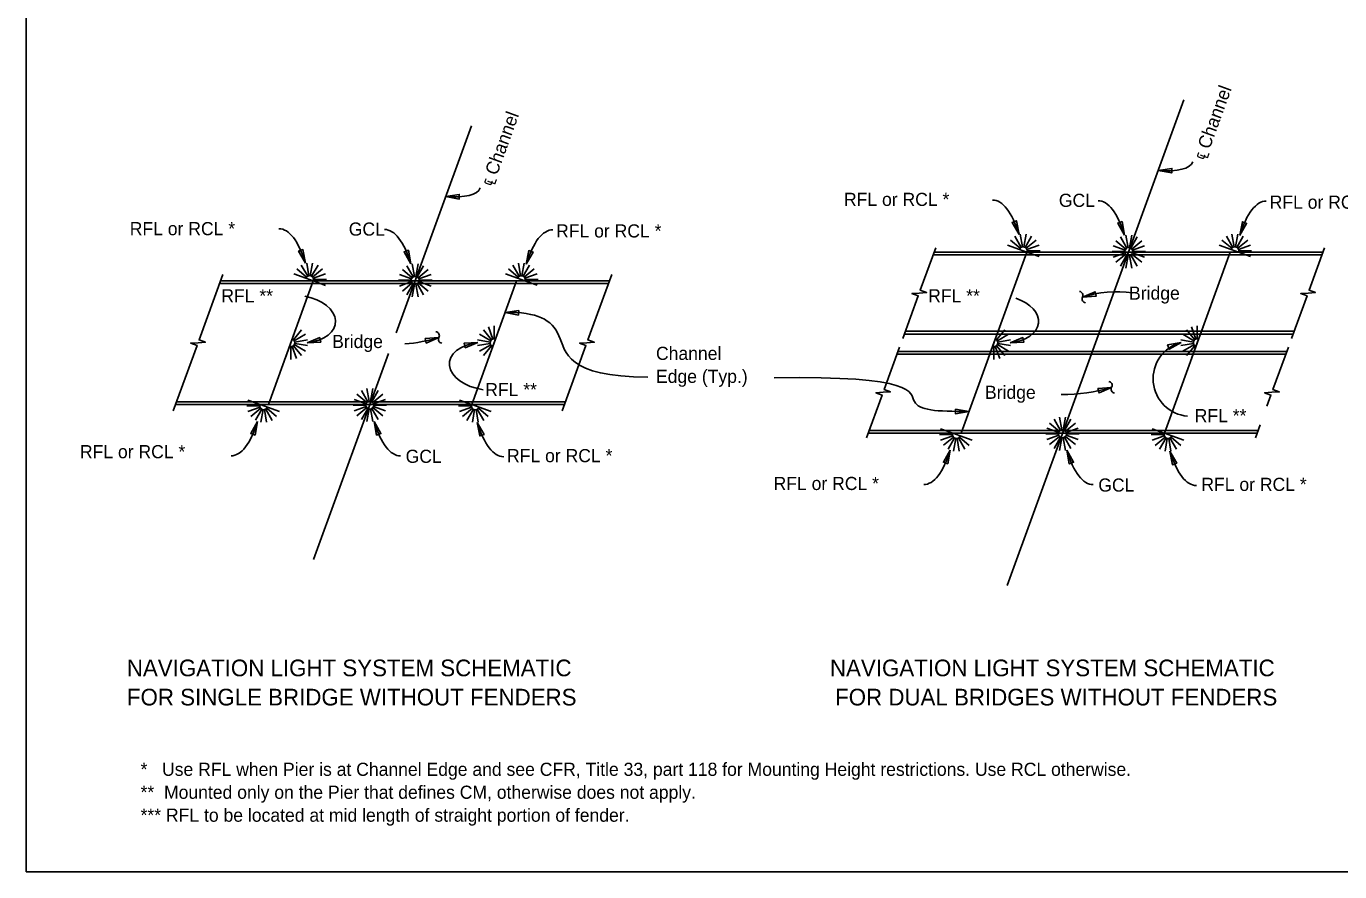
# Model space of a CAD drawing. Extents: x 0 to 1539, y 0 to 973.
# Drawn here: x 0 to 756, y 0 to 486 of the extents above; entities that cross this region are included whole.
import ezdxf

# ---------------------------------------------------------------- set-up
doc = ezdxf.new("R2010")
doc.units = 0
for name, color, linetype in [('Dimension', 7, 'Continuous'), ('Miscellaneous', 7, 'Continuous'), ('Miscellaneous1', 7, 'Continuous'), ('NavLight', 7, 'Continuous'), ('SupstrConc', 7, 'Continuous'), ('TextStructures', 7, 'Continuous')]:
    doc.layers.add(name, color=color, linetype=linetype)

msp = doc.modelspace()

# ---------------------------------------------------------------- linework, layer by layer
at = {"layer": 'Dimension'}
for points in [[(0, 0), (1539.4, 0), (1539.4, 972.98), (0, 972.98)], [(651.82, 403.57), (659.6, 402.1), (659.65, 404.75)], [(241.49, 388.54), (249.27, 387.07), (249.32, 389.71)], [(571.62, 366.77), (570.14, 374.55), (567.66, 373.63)], [(632.39, 366.36), (630.92, 374.15), (628.44, 373.23)], [(698.77, 366.2), (702.69, 373.08), (700.21, 373.99)], [(160.74, 350.23), (159.26, 358.01), (156.78, 357.09)], [(221.52, 349.82), (220.04, 357.6), (217.56, 356.68)], [(287.89, 349.66), (291.81, 356.53), (289.33, 357.44)], [(608.16, 330.66), (616.06, 331.21), (615.44, 333.78)], [(283.51, 320.29), (275.75, 321.86), (283.6, 322.94)], [(161.69, 304.25), (169.59, 304.8), (168.97, 307.37)], [(237.58, 307.39), (229.69, 306.75), (230.34, 304.18)], [(260.04, 304.6), (252.14, 304.05), (252.76, 301.48)], [(566.55, 304.25), (574.45, 304.8), (573.83, 307.37)], [(664.91, 304.59), (657.12, 303.16), (658.03, 300.67)], [(624.96, 278.73), (617.07, 278.09), (617.72, 275.52)], [(534.98, 266.17), (542.79, 264.82), (534.97, 263.52)], [(133.18, 259.05), (129.26, 252.18), (131.74, 251.27)], [(200.23, 259.02), (201.7, 251.24), (204.18, 252.16)], [(259.65, 258.53), (263.57, 251.65), (261.09, 250.74)], [(532.02, 242.51), (528.09, 235.63), (530.58, 234.72)], [(599.06, 242.48), (600.54, 234.69), (603.02, 235.61)], [(658.49, 241.98), (662.41, 235.11), (659.93, 234.2)]]:
    msp.add_lwpolyline(points, close=True, dxfattribs=at)
for points in [[(504.66, 306.82), (513.6, 331.38), (509.96, 332.7), (514.18, 332.96), (518.39, 333.22), (514.75, 334.55), (523.66, 359.02)], [(728.54, 306.82), (737.48, 331.38), (733.84, 332.7), (738.06, 332.96), (742.28, 333.22), (738.64, 334.55), (747.54, 359.02)], [(84.65, 265.19), (98.35, 302.83), (94.71, 304.16), (98.93, 304.42), (103.15, 304.68), (99.51, 306.01), (113.22, 343.69)], [(308.53, 265.19), (322.23, 302.83), (318.59, 304.16), (322.81, 304.42), (327.03, 304.68), (323.39, 306.01), (337.11, 343.69)], [(483.88, 249.73), (492.82, 274.29), (489.18, 275.62), (493.4, 275.88), (497.62, 276.14), (493.98, 277.46), (502.88, 301.93)], [(714.37, 267.87), (716.71, 274.29), (713.06, 275.62), (717.28, 275.88), (721.5, 276.14), (717.86, 277.46), (726.77, 301.93)], [(707.77, 249.73), (710.5, 257.24)]]:
    msp.add_lwpolyline(points, dxfattribs=at)
for centre, radius, start, end in [((606.2, 331.7), 2.24, 331.78441, 83.51163), ((627.83, 268.65), 65.06, 81.92792, 107.60511), ((610.14, 329.58), 2.24, 151.78441, 263.51163), ((235.62, 308.51), 2.24, 330.78819, 82.51541), ((209.68, 400.92), 97.6, 274.88318, 286.60889), ((239.52, 306.33), 2.24, 150.78819, 262.51541), ((670.44, 283.7), 21.61, 104.83071, 265.42671), ((623, 279.85), 2.24, 330.78819, 82.51541), ((597.07, 372.26), 97.6, 269.35418, 286.60889), ((626.91, 277.67), 2.24, 150.78819, 262.51541)]:
    msp.add_arc(centre, radius, start, end, dxfattribs=at)
for centre, major_axis, ratio, start_param, end_param in [((606.74, 434.59), (-65, 26.05), 0.265294, 2.43766, 3.141592), ((196.41, 419.56), (-65, 26.05), 0.265294, 2.43766, 3.141592), ((557.29, 329.23), (0.91, -57.27), 0.343516, 2.28027, 3.141592), ((618.06, 328.82), (0.91, -57.27), 0.343516, 2.28027, 3.141592), ((713.1, 328.65), (-0.91, -57.27), 0.343516, 3.141594, 4.002916), ((146.41, 312.69), (0.91, -57.27), 0.343516, 2.28027, 3.141592), ((207.18, 312.28), (0.91, -57.27), 0.343516, 2.28027, 3.141592), ((302.22, 312.11), (-0.91, -57.27), 0.343516, 3.141594, 4.002916), ((155.21, 317.92), (-22.85, 1.95), 0.604289, 1.909459, 4.535813), ((560.06, 317.92), (-22.85, 1.95), 0.604289, 1.909459, 4.325024), ((266.52, 290.93), (22.85, -1.95), 0.604289, 1.909459, 4.612762), ((118.85, 296.6), (0.91, 57.27), 0.343516, 3.141594, 4.002916), ((214.56, 296.56), (-0.91, 57.27), 0.343516, 2.28027, 3.141592), ((273.98, 296.07), (-0.91, 57.27), 0.343516, 2.28027, 3.141592), ((517.69, 280.06), (0.91, 57.27), 0.343516, 3.141594, 4.002916), ((613.4, 280.02), (-0.91, 57.27), 0.343516, 2.28027, 3.141592), ((672.82, 279.53), (-0.91, 57.27), 0.343516, 2.28027, 3.141592)]:
    msp.add_ellipse(centre, major_axis=major_axis, ratio=ratio, start_param=start_param, end_param=end_param, dxfattribs=at)
for points in [[(357.87, 284.65), (310.81, 284.65), (310.81, 313.53), (294.38, 322.09), (275.75, 321.86)], [(430.58, 284.17), (513.09, 285.6), (504.39, 265.81), (523.64, 264.88), (542.79, 264.82)]]:
    msp.add_open_spline(points, degree=3, dxfattribs=at)
at = {"layer": 'Miscellaneous'}
for p, q in [((615.73, 304.42), (666.61, 444.22)), ((212.93, 310.07), (256.28, 429.19)), ((576.16, 356.5), (538.24, 252.34)), ((693.22, 356.5), (655.3, 252.34)), ((165.28, 339.96), (139.4, 268.88)), ((282.34, 339.96), (256.46, 268.88)), ((564.85, 164.62), (615.73, 304.42)), ((165.46, 179.65), (208.61, 298.2))]:
    msp.add_line(p, q, dxfattribs=at)
at = {"layer": 'Miscellaneous1'}
msp.add_lwpolyline([(0, 972.98), (1539.4, 972.98), (1539.4, 0), (0, 0)], close=True, dxfattribs=at)
at = {"layer": 'NavLight'}
for p, q in [((572.32, 358.73), (566.65, 363.49)), ((572.92, 359.24), (569.22, 365.65)), ((573.66, 359.5), (572.37, 366.79)), ((574.44, 359.5), (575.72, 366.79)), ((575.17, 359.24), (578.87, 365.65)), ((575.77, 358.73), (581.44, 363.49)), ((633.1, 358.32), (627.43, 363.08)), ((633.7, 358.83), (630, 365.24)), ((634.43, 359.09), (633.15, 366.38)), ((635.21, 359.09), (636.5, 366.38)), ((635.95, 358.83), (639.65, 365.24)), ((636.58, 358.33), (642.25, 363.09)), ((694.13, 358.73), (688.46, 363.49)), ((694.74, 359.24), (691.03, 365.65)), ((695.5, 359.49), (694.21, 366.78)), ((696.28, 359.49), (697.57, 366.78)), ((697.02, 359.22), (700.72, 365.63)), ((697.61, 358.72), (703.28, 363.48)), ((571.93, 358.06), (564.98, 360.59)), ((576.16, 356.5), (571.93, 358.06)), ((576.19, 356.49), (583.14, 353.96)), ((576.2, 358.05), (583.15, 360.59)), ((576.33, 357.27), (583.73, 357.27)), ((632.57, 356.88), (625.17, 356.88)), ((632.71, 357.65), (625.75, 360.18)), ((632.71, 356.11), (625.75, 353.58)), ((636.97, 357.64), (643.93, 360.18)), ((636.97, 356.11), (643.93, 353.58)), ((637.1, 356.89), (644.51, 356.89)), ((693.74, 358.04), (686.78, 360.57)), ((693.77, 358.03), (698.01, 356.5)), ((698.01, 358.04), (704.96, 360.57)), ((698.01, 356.5), (704.96, 353.97)), ((698.14, 357.27), (705.54, 357.27)), ((162.04, 342.69), (158.34, 349.11)), ((162.78, 342.96), (161.49, 350.25)), ((163.56, 342.96), (164.84, 350.25)), ((164.29, 342.69), (167.99, 349.11)), ((222.82, 342.29), (219.12, 348.7)), ((223.55, 342.55), (222.27, 349.84)), ((224.33, 342.55), (225.62, 349.84)), ((225.07, 342.29), (228.77, 348.7)), ((283.86, 342.7), (280.16, 349.11)), ((284.62, 342.95), (283.34, 350.24)), ((285.4, 342.95), (286.69, 350.24)), ((286.14, 342.68), (289.84, 349.09)), ((633.1, 355.43), (627.43, 350.67)), ((633.7, 354.93), (630, 348.52)), ((634.43, 354.66), (633.15, 347.37)), ((635.21, 354.66), (636.5, 347.37)), ((635.95, 354.93), (639.65, 348.52)), ((636.58, 355.42), (642.25, 350.67)), ((161.05, 341.52), (154.1, 344.05)), ((161.44, 342.19), (155.77, 346.95)), ((165.28, 339.96), (161.05, 341.52)), ((164.89, 342.19), (170.56, 346.95)), ((165.32, 341.51), (172.27, 344.04)), ((165.45, 340.73), (172.85, 340.73)), ((221.69, 340.34), (214.29, 340.34)), ((221.83, 341.11), (214.87, 343.64)), ((222.22, 341.78), (216.55, 346.54)), ((225.7, 341.79), (231.37, 346.55)), ((226.09, 341.1), (233.05, 343.63)), ((226.23, 340.35), (233.63, 340.35)), ((282.86, 341.5), (275.91, 344.03)), ((283.25, 342.19), (277.58, 346.94)), ((282.89, 341.49), (287.13, 339.96)), ((286.74, 342.18), (292.41, 346.94)), ((287.13, 341.5), (294.08, 344.03)), ((287.26, 340.73), (294.66, 340.73)), ((165.31, 339.95), (172.26, 337.42)), ((221.83, 339.57), (214.87, 337.04)), ((222.22, 338.89), (216.55, 334.13)), ((222.82, 338.39), (219.12, 331.98)), ((223.55, 338.12), (222.27, 330.83)), ((224.33, 338.12), (225.62, 330.83)), ((225.07, 338.39), (228.77, 331.98)), ((225.7, 338.88), (231.37, 334.12)), ((226.09, 339.57), (233.05, 337.04)), ((287.13, 339.96), (294.08, 337.43)), ((153.11, 306.53), (155.64, 313.49)), ((153.79, 306.14), (158.55, 311.81)), ((267.95, 306.14), (263.2, 311.81)), ((268.63, 306.53), (266.1, 313.49)), ((269.4, 306.67), (269.4, 314.07)), ((270.17, 306.53), (272.7, 313.49)), ((557.97, 306.53), (560.5, 313.49)), ((558.65, 306.14), (563.4, 311.81)), ((672.81, 306.14), (668.05, 311.81)), ((673.49, 306.53), (670.96, 313.49)), ((674.26, 306.67), (674.26, 314.07)), ((675.03, 306.53), (677.56, 313.49)), ((151.56, 302.31), (153.11, 306.53)), ((153.79, 302.7), (158.55, 297.03)), ((154.29, 305.55), (160.7, 309.25)), ((154.29, 303.29), (160.7, 299.59)), ((154.56, 304.81), (161.85, 306.1)), ((154.56, 304.03), (161.85, 302.74)), ((267.18, 304.81), (259.89, 306.1)), ((267.18, 304.03), (259.89, 302.74)), ((267.43, 303.27), (261.02, 299.56)), ((267.45, 305.55), (261.04, 309.25)), ((267.95, 302.66), (263.19, 296.99)), ((268.65, 302.3), (270.17, 306.53)), ((556.42, 302.31), (557.97, 306.53)), ((558.65, 302.7), (563.4, 297.03)), ((559.15, 305.55), (565.56, 309.25)), ((559.15, 303.29), (565.56, 299.59)), ((559.42, 304.81), (566.71, 306.1)), ((559.42, 304.03), (566.71, 302.74)), ((672.04, 304.81), (664.75, 306.1)), ((672.04, 304.03), (664.75, 302.74)), ((672.29, 303.27), (665.88, 299.56)), ((672.31, 305.55), (665.9, 309.25)), ((672.8, 302.66), (668.05, 296.99)), ((673.5, 302.3), (675.03, 306.53)), ((151.55, 302.28), (149.01, 295.32)), ((152.33, 302.14), (152.33, 294.74)), ((153.11, 302.27), (155.64, 295.31)), ((268.63, 302.27), (266.1, 295.31)), ((556.4, 302.28), (553.87, 295.32)), ((557.18, 302.14), (557.18, 294.74)), ((557.97, 302.27), (560.5, 295.31)), ((673.49, 302.27), (670.96, 295.31)), ((196.07, 269.95), (190.4, 274.71)), ((196.67, 270.45), (192.97, 276.86)), ((197.41, 270.72), (196.12, 278.01)), ((198.19, 270.72), (199.47, 278.01)), ((198.92, 270.45), (202.62, 276.86)), ((199.56, 269.96), (205.23, 274.72)), ((134.48, 268.11), (127.08, 268.11)), ((134.62, 268.88), (127.66, 271.41)), ((134.62, 267.34), (127.66, 264.81)), ((135.01, 266.66), (129.34, 261.9)), ((135.6, 266.16), (131.9, 259.75)), ((138.85, 267.35), (134.62, 268.88)), ((136.34, 265.89), (135.05, 258.6)), ((137.12, 265.89), (138.41, 258.6)), ((137.88, 266.14), (141.59, 259.73)), ((138.49, 266.65), (144.16, 261.9)), ((138.88, 267.34), (145.84, 264.81)), ((195.55, 268.5), (188.15, 268.5)), ((195.68, 269.27), (188.73, 271.8)), ((195.68, 267.73), (188.73, 265.2)), ((196.07, 267.06), (190.4, 262.3)), ((196.67, 266.55), (192.97, 260.14)), ((197.41, 266.29), (196.12, 259)), ((198.19, 266.29), (199.47, 259)), ((198.92, 266.55), (202.62, 260.14)), ((199.56, 267.05), (205.23, 262.29)), ((199.95, 269.27), (206.9, 271.8)), ((199.95, 267.74), (206.9, 265.21)), ((200.08, 268.52), (207.48, 268.52)), ((256.29, 268.11), (248.89, 268.11)), ((256.42, 267.33), (249.47, 264.8)), ((256.43, 268.89), (249.48, 271.42)), ((256.85, 266.65), (251.18, 261.89)), ((257.45, 266.15), (253.75, 259.74)), ((256.46, 268.88), (260.69, 267.32)), ((258.18, 265.88), (256.9, 258.59)), ((258.96, 265.88), (260.25, 258.59)), ((259.7, 266.15), (263.4, 259.74)), ((260.3, 266.65), (265.97, 261.89)), ((260.69, 267.32), (267.64, 264.79)), ((594.91, 253.41), (589.24, 258.17)), ((595.51, 253.91), (591.81, 260.32)), ((596.25, 254.18), (594.96, 261.47)), ((597.03, 254.18), (598.31, 261.47)), ((597.76, 253.91), (601.46, 260.32)), ((598.39, 253.42), (604.06, 258.17)), ((533.32, 251.57), (525.92, 251.57)), ((533.45, 252.34), (526.5, 254.87)), ((533.45, 250.8), (526.5, 248.27)), ((533.84, 250.12), (528.17, 245.36)), ((534.44, 249.62), (530.74, 243.21)), ((537.69, 250.81), (533.45, 252.34)), ((536.72, 249.6), (540.42, 243.19)), ((537.33, 250.11), (543, 245.35)), ((537.72, 250.8), (544.67, 248.27)), ((594.39, 251.96), (586.98, 251.96)), ((594.52, 252.73), (587.57, 255.26)), ((594.52, 251.19), (587.57, 248.66)), ((594.91, 250.52), (589.24, 245.76)), ((595.51, 250.01), (591.81, 243.6)), ((596.25, 249.75), (594.96, 242.46)), ((597.03, 249.75), (598.31, 242.46)), ((597.76, 250.01), (601.46, 243.6)), ((598.39, 250.51), (604.06, 245.75)), ((598.79, 252.73), (605.74, 255.26)), ((598.79, 251.2), (605.74, 248.66)), ((598.92, 251.98), (606.32, 251.98)), ((655.13, 251.57), (647.73, 251.57)), ((655.26, 250.79), (648.31, 248.25)), ((655.27, 252.35), (648.32, 254.88)), ((655.69, 250.11), (650.02, 245.35)), ((656.29, 249.6), (652.59, 243.19)), ((655.3, 252.34), (659.53, 250.78)), ((658.54, 249.6), (662.24, 243.19)), ((659.14, 250.11), (664.81, 245.35)), ((659.53, 250.78), (666.48, 248.25)), ((535.18, 249.35), (533.89, 242.06)), ((535.96, 249.35), (537.24, 242.06)), ((657.02, 249.34), (655.74, 242.05)), ((657.8, 249.34), (659.09, 242.05))]:
    msp.add_line(p, q, dxfattribs=at)
for centre in [(634.82, 356.88), (223.94, 340.34), (197.8, 268.5), (596.64, 251.96)]:
    msp.add_circle(centre, 2.25, dxfattribs=at)
for centre, start, end in [((574.05, 357.29), 339.6086, 160), ((695.89, 357.27), 340, 160.3914), ((163.17, 340.75), 339.6086, 160), ((285.01, 340.73), 340, 160.3914), ((152.34, 304.42), 249.6086, 70), ((269.4, 304.42), 70, 250.3914), ((557.2, 304.42), 249.6086, 70), ((674.26, 304.42), 70, 250.3914), ((136.73, 268.11), 160, 340.3914), ((258.57, 268.09), 159.6086, 340), ((535.57, 251.57), 160, 340.3914), ((657.41, 251.55), 159.6086, 340)]:
    msp.add_arc(centre, 2.25, start, end, dxfattribs=at)
at = {"layer": 'SupstrConc'}
for p, q in [((522.74, 356.5), (746.63, 356.5)), ((522.18, 354.96), (746.07, 354.96)), ((111.3, 338.42), (335.19, 338.42)), ((111.87, 339.96), (335.75, 339.96)), ((730.05, 310.96), (506.17, 310.96)), ((729.49, 309.42), (505.61, 309.42)), ((725.29, 297.88), (501.41, 297.88)), ((725.85, 299.42), (501.97, 299.42)), ((85.99, 268.88), (309.88, 268.88)), ((86.55, 270.42), (310.44, 270.42)), ((708.71, 252.34), (484.83, 252.34)), ((709.28, 253.88), (485.39, 253.88))]:
    msp.add_line(p, q, dxfattribs=at)

# ---------------------------------------------------------------- texts
at = {"layer": 'Dimension'}
for s, height, p in [('NAVIGATION LIGHT SYSTEM SCHEMATIC', 9.6, (57.9, 112.47)), ('NAVIGATION LIGHT SYSTEM SCHEMATIC', 9.6, (462.76, 112.47)), ('FOR SINGLE BRIDGE WITHOUT FENDERS', 9.6, (57.95, 95.67)), ('FOR DUAL BRIDGES WITHOUT FENDERS', 9.6, (465.72, 95.67)), ('*   Use RFL when Pier is at Channel Edge and see CFR, Title 33, part 118 for Mounting Height restrictions. Use RCL otherwise.', 7.56002, (65.82, 55.16)), ('**  Mounted only on the Pier that defines CM, otherwise does not apply.', 7.56, (65.82, 41.96)), ('*** RFL to be located at mid length of straight portion of fender.', 7.56, (65.82, 28.76))]:
    msp.add_text(s, height=height, dxfattribs=at).set_placement(p)
at = {"layer": 'TextStructures'}
for p in [(678.97, 408.83), (268.64, 393.79)]:
    msp.add_text('℄ Channel', height=7.56, rotation=70, dxfattribs=at).set_placement(p)
for s, p in [('RFL or RCL *', (470.83, 383.11)), ('GCL', (594.55, 382.56)), ('RFL or RCL *', (715.95, 381.51)), ('RFL or RCL *', (59.58, 366.27)), ('GCL', (185.69, 366.02)), ('RFL or RCL *', (305.07, 364.96)), ('RFL **', (112.3, 327.63)), ('RFL **', (519.31, 327.63)), ('Bridge ', (634.98, 329.18)), ('Bridge ', (176.13, 301.34)), ('Channel', (362.58, 294.51)), ('Edge (Typ.)', (362.58, 281.28)), ('RFL **', (264.27, 273.65)), ('Bridge ', (552.03, 272.1)), ('RFL **', (672.78, 258.66)), ('RFL or RCL *', (30.89, 237.93)), ('GCL', (218.44, 235.26)), ('RFL or RCL *', (276.83, 235.66)), ('RFL or RCL *', (430.3, 219.64)), ('GCL', (617.27, 218.72)), ('RFL or RCL *', (676.6, 219.12))]:
    msp.add_text(s, height=7.56, dxfattribs=at).set_placement(p)

doc.saveas('drawing.dxf')
